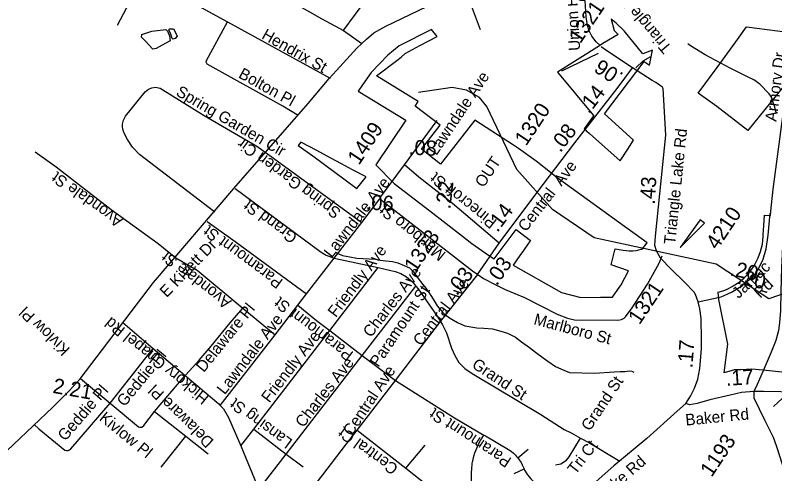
# Model space of a CAD drawing. Extents: x 1715610 to 1720914, y 798298 to 802505.
# Drawn here: x 1715768.9 to 1715906.1, y 799622.4 to 799705.3 of the extents above; entities that cross this region are included whole.
import ezdxf

# ---------------------------------------------------------------- set-up
doc = ezdxf.new("R2010")
doc.units = 0
doc.layers.add('Default', color=7, linetype='Continuous')

msp = doc.modelspace()

# ---------------------------------------------------------------- linework, layer by layer
at = {"layer": 'Default'}
for p, q in [((1715828.11, 799702.49), (1715833.65, 799710.05)), ((1715850.49, 799709.16), (1715852.87, 799702.73)), ((1715807.26, 799704.1), (1715825.78, 799693.93)), ((1715839.23, 799678.27), (1715845.1, 799686.27)), ((1715814.2, 799680.43), (1715831.47, 799667.88)), ((1715834.87, 799672.41), (1715839.23, 799678.27)), ((1715831.47, 799667.88), (1715834.75, 799672.15)), ((1715826.48, 799661.4), (1715831.47, 799667.88)), ((1715852.41, 799658.44), (1715856.31, 799664.11)), ((1715821.52, 799654.94), (1715826.48, 799661.4)), ((1715826.48, 799661.4), (1715834.47, 799659.7)), ((1715825.7, 799648.31), (1715834.47, 799659.7)), ((1715845.7, 799649.97), (1715852.47, 799658.43)), ((1715831.58, 799643.8), (1715841.26, 799656.32)), ((1715819.95, 799652.91), (1715821.52, 799654.94)), ((1715815.84, 799647.56), (1715819.95, 799652.91)), ((1715810, 799652.38), (1715815.84, 799647.56)), ((1715837.55, 799639.28), (1715845.7, 799649.97)), ((1715788.35, 799649.79), (1715793.84, 799645.1)), ((1715805.94, 799634.77), (1715815.84, 799647.56)), ((1715811.99, 799630.49), (1715825.7, 799648.31)), ((1715825.7, 799648.31), (1715831.58, 799643.8)), ((1715786.04, 799635.17), (1715793.84, 799645.1)), ((1715793.84, 799645.1), (1715799.59, 799640.22)), ((1715817.84, 799625.99), (1715831.58, 799643.8)), ((1715831.58, 799643.8), (1715837.55, 799639.28)), ((1715780.67, 799639.65), (1715786.04, 799635.17)), ((1715794.07, 799633.66), (1715799.59, 799640.22)), ((1715830.66, 799630.31), (1715837.55, 799639.28)), ((1715905.84, 799634.58), (1715907.49, 799636.09)), ((1715794.07, 799633.66), (1715799.73, 799629.21)), ((1715809.65, 799627.47), (1715811.99, 799630.49)), ((1715811.99, 799630.49), (1715817.84, 799625.99)), ((1715830.66, 799630.31), (1715839.43, 799623.43)), ((1715795.28, 799623.61), (1715799.73, 799629.21)), ((1715799.73, 799629.21), (1715803.72, 799626.06)), ((1715809.65, 799627.47), (1715812.88, 799619.6)), ((1715839.43, 799623.43), (1715842.93, 799627.63)), ((1715859.67, 799625.33), (1715861.53, 799626.9)), ((1715812.88, 799619.6), (1715817.84, 799625.99)), ((1715817.84, 799625.99), (1715820.91, 799623.71)), ((1715839.43, 799623.43), (1715843.49, 799620.24)), ((1715859.02, 799622.48), (1715860.8, 799623.32))]:
    msp.add_line(p, q, dxfattribs=at)
for points in [[(1715831.51, 799700.23), (1715832.34, 799701), (1715833.68, 799702.12), (1715835.83, 799703.33), (1715846.23, 799708.39), (1715860.3, 799713.75), (1715865.13, 799715.4), (1715867.52, 799716.4), (1715869.21, 799717.62), (1715871.02, 799719.25), (1715879.25, 799726.89), (1715883.32, 799730.86), (1715890.44, 799737.32), (1715894.28, 799741.38)], [(1715788.95, 799724.59), (1715793.74, 799721.98), (1715797.1, 799720.24), (1715801.98, 799717.56), (1715807.32, 799714.53), (1715812.73, 799711.18), (1715818, 799708.29), (1715824.25, 799704.66), (1715828.17, 799702.54), (1715831.51, 799700.23)], [(1715874.55, 799699.85), (1715874.54, 799699.85), (1715873.83, 799700.51), (1715873.06, 799701.55), (1715872.58, 799702.48), (1715872.26, 799703.49), (1715872.02, 799705.03), (1715871.83, 799707.93), (1715871.03, 799707.99), (1715870.56, 799708.22), (1715870.37, 799708.71), (1715870.07, 799710.93), (1715869.79, 799711.87), (1715869.36, 799712.47), (1715869.37, 799713.25), (1715869.78, 799713.9)], [(1715787.37, 799703.55), (1715790.65, 799709.73), (1715792.02, 799712.87)], [(1715792.02, 799712.87), (1715793.45, 799711.92), (1715799.16, 799708.59), (1715807.26, 799704.1)], [(1715820.01, 799687.2), (1715817.22, 799688.86), (1715803.57, 799696.47), (1715803.4, 799696.85), (1715803.46, 799697.15), (1715807.26, 799704.1)], [(1715877.4, 799703.9), (1715876.52, 799704.61), (1715877.07, 799702.55), (1715877.76, 799701.83), (1715875.03, 799700.21), (1715874.4, 799699.81), (1715866.81, 799695), (1715873.31, 799687.17), (1715873.36, 799687.11), (1715871.62, 799684.81), (1715872.59, 799683.97), (1715878.15, 799679), (1715879.52, 799681.13), (1715880.56, 799682.76), (1715875.3, 799687.48), (1715882.5, 799696.94), (1715883.43, 799696.27), (1715884, 799698.98), (1715882.26, 799698.35), (1715878.9, 799702.5), (1715877.4, 799703.9)], [(1715877.4, 799703.9), (1715876.52, 799704.61), (1715877.07, 799702.55), (1715877.76, 799701.83), (1715875.03, 799700.21), (1715874.4, 799699.81), (1715866.81, 799695), (1715873.31, 799687.17), (1715873.36, 799687.11), (1715871.62, 799684.81), (1715872.59, 799683.97), (1715878.15, 799679), (1715879.52, 799681.13), (1715880.56, 799682.76), (1715875.3, 799687.48), (1715882.5, 799696.94), (1715883.43, 799696.27), (1715884, 799698.98), (1715882.26, 799698.35), (1715878.9, 799702.5), (1715877.4, 799703.9)], [(1715793.75, 799699.2), (1715792.39, 799700.72), (1715791.73, 799701.36), (1715791.76, 799701.82), (1715793.55, 799702.46), (1715796.1, 799702.72), (1715796.4, 799702.45), (1715796.77, 799701.59), (1715796.87, 799700.71), (1715795.44, 799699.9), (1715794.34, 799699.28), (1715794.03, 799699.22), (1715793.75, 799699.2)], [(1715797.27, 799701.12), (1715796.96, 799702.08), (1715796.65, 799702.63), (1715796.85, 799702.83), (1715797.46, 799702.83), (1715797.84, 799702.17), (1715798.17, 799701.54), (1715797.81, 799701.1), (1715797.38, 799700.98), (1715797.27, 799701.12)], [(1715830.81, 799691.57), (1715839.44, 799686.37), (1715834.05, 799678.25), (1715837.36, 799674.93), (1715843.8, 799669.96), (1715849.68, 799665.38), (1715851.35, 799664.08), (1715854.37, 799661.96), (1715855.4, 799661.27), (1715859.37, 799666.58), (1715861.97, 799664.61), (1715861.59, 799664.09), (1715860.67, 799662.81), (1715860.02, 799661.88), (1715858.8, 799660.13), (1715867.58, 799655.19), (1715871.05, 799654.31), (1715874.57, 799654.33), (1715876.74, 799654.33), (1715877.03, 799654.72), (1715878.34, 799656.61), (1715879.65, 799659.1), (1715876.54, 799660.18), (1715877.27, 799663.11), (1715878.68, 799662.83), (1715879.22, 799662.77), (1715879.77, 799662.74), (1715880.46, 799662.76), (1715881.01, 799662.82), (1715881.55, 799662.91), (1715881.95, 799663.01), (1715882.11, 799663.04), (1715883.03, 799664.2), (1715881.96, 799664.96), (1715877.85, 799667.89), (1715866.51, 799676.09), (1715865.55, 799676.88), (1715863.01, 799678.91), (1715859.81, 799681.24), (1715858.87, 799681.85), (1715856.01, 799683.7), (1715851.89, 799686.38), (1715845.71, 799678.38), (1715842.29, 799681.11), (1715845.63, 799685.46), (1715841.1, 799688.88), (1715841.68, 799689.75), (1715834.14, 799694.35), (1715837.79, 799697.11), (1715838.63, 799697.75), (1715839.33, 799698.38), (1715841.99, 799699.83), (1715845.11, 799701.48), (1715844.06, 799702.75), (1715838.24, 799699.79), (1715836.2, 799698.07), (1715833.17, 799694.95), (1715831.6, 799692.71), (1715830.81, 799691.57)], [(1715830.81, 799691.57), (1715839.44, 799686.37), (1715834.05, 799678.25), (1715837.36, 799674.93), (1715843.8, 799669.96), (1715849.68, 799665.38), (1715851.35, 799664.08), (1715854.37, 799661.96), (1715855.4, 799661.27), (1715859.37, 799666.58), (1715861.97, 799664.61), (1715861.59, 799664.09), (1715860.67, 799662.81), (1715860.02, 799661.88), (1715858.8, 799660.13), (1715867.58, 799655.19), (1715871.05, 799654.31), (1715874.57, 799654.33), (1715876.74, 799654.33), (1715877.03, 799654.72), (1715878.34, 799656.61), (1715879.65, 799659.1), (1715876.54, 799660.18), (1715877.27, 799663.11), (1715878.68, 799662.83), (1715879.22, 799662.77), (1715879.77, 799662.74), (1715880.46, 799662.76), (1715881.01, 799662.82), (1715881.55, 799662.91), (1715881.95, 799663.01), (1715882.11, 799663.04), (1715883.03, 799664.2), (1715881.96, 799664.96), (1715877.85, 799667.89), (1715866.51, 799676.09), (1715865.55, 799676.88), (1715863.01, 799678.91), (1715859.81, 799681.24), (1715858.87, 799681.85), (1715856.01, 799683.7), (1715851.89, 799686.38), (1715845.71, 799678.38), (1715842.29, 799681.11), (1715845.63, 799685.46), (1715841.1, 799688.88), (1715841.68, 799689.75), (1715834.14, 799694.35), (1715837.79, 799697.11), (1715838.63, 799697.75), (1715839.33, 799698.38), (1715841.99, 799699.83), (1715845.11, 799701.48), (1715844.06, 799702.75), (1715838.24, 799699.79), (1715836.2, 799698.07), (1715833.17, 799694.95), (1715831.6, 799692.71), (1715830.81, 799691.57)], [(1715919.1, 799639.53), (1715903.98, 799641.14), (1715901.84, 799641.35), (1715899.98, 799641.22), (1715898.82, 799641.19), (1715896.95, 799640.7), (1715897.6, 799645.85), (1715895.95, 799653.93), (1715895.83, 799655.24), (1715896.74, 799655.52), (1715897.45, 799655.8), (1715898.37, 799656.26), (1715898.57, 799656.38), (1715899.64, 799657.09), (1715900.52, 799657.82), (1715901.32, 799658.64), (1715902.08, 799659.64), (1715902.56, 799660.48), (1715903.08, 799661.45), (1715903.51, 799662.6), (1715903.83, 799663.91), (1715903.98, 799665.3), (1715904, 799665.64), (1715904.09, 799667.29), (1715904.2, 799669.15), (1715905.29, 799669.09), (1715905.37, 799669.89), (1715905.79, 799673.89), (1715908.36, 799693.36), (1715901.2, 799684.46), (1715895.58, 799688.81), (1715892.25, 799691.21), (1715895.64, 799695.89), (1715899.01, 799700.54), (1715900.95, 799703.22), (1715908.4, 799702.28)], [(1715919.1, 799639.53), (1715903.98, 799641.14), (1715901.84, 799641.35), (1715899.98, 799641.22), (1715898.82, 799641.19), (1715896.95, 799640.7), (1715897.6, 799645.85), (1715895.95, 799653.93), (1715895.83, 799655.24), (1715896.74, 799655.52), (1715897.45, 799655.8), (1715898.37, 799656.26), (1715898.57, 799656.38), (1715899.64, 799657.09), (1715900.52, 799657.82), (1715901.32, 799658.64), (1715902.08, 799659.64), (1715902.56, 799660.48), (1715903.08, 799661.45), (1715903.51, 799662.6), (1715903.83, 799663.91), (1715903.98, 799665.3), (1715904, 799665.64), (1715904.09, 799667.29), (1715904.2, 799669.15), (1715905.29, 799669.09), (1715905.37, 799669.89), (1715905.79, 799673.89), (1715908.36, 799693.36), (1715901.2, 799684.46), (1715895.58, 799688.81), (1715892.25, 799691.21), (1715895.64, 799695.89), (1715899.01, 799700.54), (1715900.95, 799703.22), (1715908.4, 799702.28)], [(1715746.87, 799606.94), (1715750.09, 799610.55), (1715755.24, 799615.32), (1715761.84, 799621.51), (1715764.95, 799624.35), (1715775.71, 799634.47), (1715778.64, 799637.42), (1715780.62, 799639.61), (1715793.86, 799657.02), (1715808.39, 799674), (1715821.8, 799689.38), (1715825.57, 799693.86), (1715826.9, 799695.32), (1715830.61, 799699.38), (1715831.51, 799700.23)], [(1715880.39, 799695.79), (1715875.77, 799698.88), (1715874.72, 799699.58)], [(1715906.34, 799687.75), (1715906.03, 799688.91), (1715905.75, 799689.73), (1715905.48, 799690.5), (1715905.05, 799691.1), (1715903.37, 799692.88), (1715902.29, 799693.62), (1715901.28, 799694.15), (1715900.56, 799694.49), (1715898.01, 799695.76), (1715893.48, 799698.16), (1715890.86, 799699.8), (1715890.36, 799700.14)], [(1715867.59, 799695.24), (1715874.24, 799698.45)], [(1715867.59, 799695.24), (1715874.24, 799698.45)], [(1715880.96, 799695.8), (1715882.28, 799697.05), (1715883.7, 799697.87)], [(1715856.31, 799664.11), (1715863.08, 799673.21), (1715869.97, 799682.23), (1715877.6, 799692.06), (1715880.39, 799695.79)], [(1715892.25, 799653.5), (1715891.76, 799654.84), (1715891.5, 799655.23), (1715889.75, 799657.07), (1715887.38, 799659.44), (1715885.45, 799661.43), (1715884.74, 799662.74), (1715884.44, 799663.68), (1715884.51, 799665.39), (1715886.41, 799683.61), (1715885.89, 799692.1), (1715885.8, 799692.33), (1715885.45, 799692.53), (1715884.57, 799693.13), (1715883.93, 799693.52), (1715880.39, 799695.79)], [(1715804.93, 799669.7), (1715791.35, 799680.17), (1715790.11, 799681.46), (1715789.17, 799682.83), (1715788.53, 799684.15), (1715788.34, 799684.73), (1715788.28, 799685.19), (1715788.29, 799685.64), (1715788.47, 799686.38), (1715788.84, 799687.05), (1715792.36, 799691.45), (1715792.97, 799691.97), (1715793.59, 799692.22), (1715794.25, 799692.29), (1715795.07, 799692.11), (1715803.04, 799687.19), (1715812.54, 799681.64), (1715814.2, 799680.43)], [(1715901.6, 799656.26), (1715895.47, 799660.35), (1715873.43, 799665.08), (1715865.94, 799670.19), (1715859.51, 799677.43), (1715854.07, 799688.85), (1715852.74, 799690.42), (1715850.38, 799691.79), (1715847.82, 799692.24), (1715841.72, 799691.36)], [(1715822.66, 799679.89), (1715830.62, 799673.98), (1715832.25, 799676.09), (1715829.84, 799677.39), (1715827.84, 799678.47), (1715825.92, 799679.49), (1715823.39, 799680.84), (1715820.49, 799682.4), (1715820.02, 799681.77), (1715822.66, 799679.89)], [(1715822.66, 799679.89), (1715830.62, 799673.98), (1715832.25, 799676.09), (1715829.84, 799677.39), (1715827.84, 799678.47), (1715825.92, 799679.49), (1715823.39, 799680.84), (1715820.49, 799682.4), (1715820.02, 799681.77), (1715822.66, 799679.89)], [(1715772.48, 799680.63), (1715776.28, 799677.91), (1715786.22, 799670.21), (1715794.73, 799664.04), (1715797.88, 799661.48)], [(1715856.31, 799664.11), (1715847.85, 799671.31), (1715841.82, 799676.03), (1715839.23, 799678.27)], [(1715808.63, 799673.98), (1715824.18, 799662.47), (1715825.03, 799661.96), (1715826.48, 799661.4)], [(1715834.75, 799672.15), (1715842.01, 799666.47), (1715851.48, 799659.14), (1715852.47, 799658.43)], [(1715892.25, 799653.5), (1715896.4, 799654.41), (1715898.23, 799655.23), (1715900.27, 799656.45), (1715901.65, 799657.72), (1715902.58, 799658.63), (1715903.19, 799659.58), (1715903.95, 799661.24), (1715904.49, 799663.1), (1715904.87, 799665.59), (1715905.21, 799669.56)], [(1715803.54, 799668.06), (1715808.62, 799664.42), (1715821.52, 799654.94)], [(1715888.99, 799663.34), (1715893.36, 799667.71), (1715892.61, 799668.32), (1715888.99, 799663.34)], [(1715888.99, 799663.34), (1715893.36, 799667.71), (1715892.61, 799668.32), (1715888.99, 799663.34)], [(1715907.92, 799666.67), (1715907.49, 799663.53), (1715907.27, 799659.67), (1715907.19, 799655.36), (1715907.08, 799651.92), (1715906.95, 799649.74), (1715906.77, 799648.31), (1715906.28, 799646.53), (1715905.43, 799644.44), (1715903.95, 799641.06), (1715902.9, 799638.56), (1715902.3, 799637.29)], [(1715826.7, 799662.47), (1715827.99, 799661.89), (1715829.35, 799661.63), (1715830.58, 799661.41), (1715831.69, 799661.33), (1715833.99, 799661.21), (1715834.83, 799661.04), (1715835.82, 799660.94), (1715837.04, 799660.78), (1715838.01, 799660.58), (1715839.16, 799660.1), (1715840.08, 799659.67), (1715840.8, 799658.95), (1715841.51, 799657.98), (1715842.53, 799656.63), (1715843.05, 799656.01), (1715843.57, 799655.22), (1715844.07, 799654.5), (1715844.53, 799653.71), (1715845.12, 799652.81), (1715845.81, 799651.97), (1715846.43, 799651.27), (1715847.3, 799650.61), (1715848.79, 799649.78), (1715850.08, 799649.2), (1715851.18, 799649.02), (1715852.25, 799648.8), (1715853.54, 799648.75), (1715855.12, 799648.66), (1715856.57, 799648.23), (1715857.8, 799647.85), (1715859.27, 799647.14), (1715860.32, 799646.3), (1715861.76, 799645.25), (1715862.85, 799644.44), (1715864.23, 799643.37), (1715865.08, 799642.78), (1715866.48, 799641.81), (1715868, 799641.17), (1715869.01, 799640.73), (1715873.54, 799640.59), (1715877.06, 799640.85), (1715878.17, 799640.92), (1715878.98, 799640.94), (1715879.84, 799641.03), (1715880.26, 799640.95), (1715880.63, 799640.8)], [(1715797.88, 799661.48), (1715801.74, 799659.22), (1715810, 799652.38)], [(1715852.47, 799658.43), (1715853.44, 799657.72), (1715855.58, 799656.62), (1715857.39, 799655.74), (1715860.85, 799654.32), (1715866.75, 799651.27), (1715868.61, 799650.55), (1715869.89, 799650.26), (1715877.71, 799650.2), (1715878.37, 799650.29), (1715878.85, 799650.53), (1715879.14, 799650.8), (1715880.29, 799652.42), (1715883.11, 799656.68), (1715885.19, 799660.49), (1715885.74, 799661.8)], [(1715834.47, 799659.7), (1715837.51, 799658.99), (1715838.56, 799658.63), (1715839.59, 799658.03), (1715840.57, 799657.18), (1715841.26, 799656.32)], [(1715948.98, 799649.69), (1715944.54, 799651.19), (1715941.43, 799650.24), (1715936.92, 799647.4), (1715930.32, 799646.42), (1715915.93, 799656.24), (1715913.57, 799656.98), (1715905, 799654.05), (1715901.6, 799656.26)], [(1715841.26, 799656.32), (1715841.65, 799655.84), (1715845.25, 799650.73), (1715845.7, 799649.97)], [(1715819.95, 799652.91), (1715823.34, 799650.12), (1715825.7, 799648.31)], [(1715890.01, 799635.12), (1715890.86, 799636.47), (1715891.59, 799637.91), (1715892.15, 799639.52), (1715892.54, 799641.44), (1715892.83, 799645.03), (1715892.85, 799646.68), (1715892.8, 799650.52), (1715892.56, 799652.25), (1715892.25, 799653.5)], [(1715799.59, 799640.22), (1715800.32, 799640.95), (1715802.11, 799642.95), (1715804.28, 799645.5), (1715807.7, 799649.71), (1715810, 799652.38)], [(1715845.7, 799649.97), (1715846.06, 799649.37), (1715846.78, 799647.89), (1715847.7, 799645.16), (1715848.29, 799643.81), (1715849.03, 799642.56), (1715850.11, 799641.47), (1715851.43, 799640.53), (1715863.81, 799633.12), (1715868.01, 799630.41), (1715869.29, 799629.81), (1715870.98, 799628.88)], [(1715799.59, 799640.22), (1715805.66, 799635.07), (1715805.94, 799634.77)], [(1715837.55, 799639.28), (1715848.24, 799632.54), (1715853.54, 799629.42)], [(1715902.3, 799637.29), (1715900.07, 799637.14), (1715898.03, 799636.62), (1715894.33, 799635.77), (1715892.04, 799635.11), (1715890.73, 799634.88), (1715890.01, 799635.12)], [(1715902.3, 799637.29), (1715902.27, 799636.17), (1715904.22, 799632.17), (1715905.78, 799629.04), (1715906.3, 799627.55), (1715907.07, 799625.31), (1715907.56, 799623.59), (1715907.9, 799621.88), (1715908.13, 799620.24), (1715908.12, 799617.9), (1715908.1, 799614.72)], [(1715909.1, 799637.14), (1715907.16, 799637.22), (1715904.01, 799637.29), (1715902.3, 799637.29)], [(1715772.41, 799631.3), (1715773.17, 799630.55), (1715777.88, 799626.71), (1715778.15, 799626.63), (1715778.44, 799626.64), (1715778.7, 799626.75), (1715778.93, 799626.94), (1715786.04, 799635.17)], [(1715786.04, 799635.17), (1715791.14, 799630.94), (1715791.43, 799630.85), (1715791.76, 799630.88), (1715792.13, 799631.13), (1715794.07, 799633.66)], [(1715890.01, 799635.12), (1715888.45, 799633.74), (1715882.95, 799628.79), (1715877.02, 799623.84), (1715871.14, 799618.71), (1715864.33, 799612.97), (1715862.85, 799611.55), (1715857.18, 799605.08), (1715851.79, 799598.24), (1715846.32, 799591.23), (1715843.76, 799587.75)], [(1715805.94, 799634.77), (1715806.49, 799634.15), (1715807.39, 799632.59), (1715809.65, 799627.47)], [(1715816.12, 799611.63), (1715818.03, 799613.96), (1715824.46, 799622.22), (1715828.54, 799627.62), (1715830.66, 799630.31)], [(1715852.04, 799618.46), (1715851.84, 799619.02), (1715851.48, 799620.28), (1715851.39, 799620.82), (1715851.33, 799621.38), (1715851.3, 799621.76), (1715851.29, 799622.15), (1715851.3, 799622.72), (1715851.34, 799623.29), (1715851.44, 799624.2), (1715851.51, 799624.6), (1715851.59, 799625.01), (1715851.74, 799625.61), (1715851.92, 799626.19), (1715852.12, 799626.78), (1715852.37, 799627.34), (1715852.63, 799627.9), (1715852.93, 799628.43), (1715853.54, 799629.42)], [(1715853.54, 799629.42), (1715853.81, 799629.26), (1715857.99, 799626.81), (1715858.44, 799626.5), (1715858.91, 799626.13), (1715859.26, 799625.8), (1715859.45, 799625.58), (1715859.67, 799625.33)], [(1715866.47, 799624.03), (1715867.43, 799624.2), (1715868.43, 799624.88), (1715868.92, 799625.47), (1715870.98, 799628.88)], [(1715870.98, 799628.88), (1715872.51, 799628.08), (1715878.08, 799624.72)], [(1715859.67, 799625.33), (1715859.93, 799624.97), (1715860.25, 799624.48), (1715860.48, 799624.06), (1715860.8, 799623.32)], [(1715860.8, 799623.32), (1715860.9, 799623.1), (1715861.01, 799622.9), (1715861.32, 799622.4), (1715861.64, 799621.96), (1715862, 799621.54), (1715862.38, 799621.16), (1715862.81, 799620.81), (1715862.99, 799620.67), (1715863.73, 799620.2)]]:
    msp.add_lwpolyline(points, dxfattribs=at)

# ---------------------------------------------------------------- texts
for s, height, rotation, p in [('Triangle Lake Rd', 2.0663, 130.2684, (1715887.59, 799699.5)), ('Union Hill Ct', 2.0663, 93.2309, (1715870.95, 799698.94)), ('1321', 2.719, 56.2051, (1715870.94, 799700.04)), ('Hendrix St', 2.066, 330.4741, (1715813.25, 799701.2)), ('Armory Dr', 2.066, 82.5782, (1715906.36, 799686.01)), ('.06', 2.719, 146.1702, (1715878.92, 799694.71)), ('Bolton Pl', 2.066, 330.8692, (1715809.06, 799694.14)), ('Lawndale Ave', 2.0663, 56.2051, (1715844.97, 799679.84)), ('.14', 2.719, 52.1742, (1715872.52, 799687.35)), ('Spring Garden Cir', 2.0663, 329.6562, (1715797.76, 799690.95)), ('1320', 2.719, 56.2051, (1715861.16, 799681.55)), ('1409', 2.719, 56.2051, (1715830.98, 799678.1)), ('.08', 2.719, 52.3595, (1715867.35, 799680.37)), ('Triangle Lake Rd', 2.0663, 84.031, (1715888.07, 799663.8)), ('Spring Garden Cir', 2.0663, 143.5611, (1715827.89, 799670.03)), ('.08', 2.719, 357.5478, (1715839.93, 799680.12)), ('OUT', 2.066, 56.2051, (1715853.47, 799674.03)), ('Central  Ave', 2.0663, 52.1888, (1715861.13, 799666.04)), ('Avondale St', 2.0663, 144.3486, (1715788.54, 799668.48)), ('Pinecroft St', 2.0663, 141.4159, (1715856.05, 799668.18)), ('Lawndale Ave', 2.0663, 52.1626, (1715826.07, 799661.33)), ('.22', 2.719, 83.413, (1715847.49, 799670.18)), ('.43', 2.719, 86.4557, (1715884.39, 799671.03)), ('Grand St', 2.066, 143.7404, (1715820.03, 799665.56)), ('.06', 2.719, 357.1316, (1715832.14, 799670.19)), ('Marlboro St', 2.0663, 141.0359, (1715846.82, 799662.32)), ('.14', 2.719, 53.3448, (1715855.99, 799665.95)), ('4210', 2.719, 56.2051, (1715895.68, 799662.78)), ('Paramount St', 2.0663, 143.3367, (1715817.42, 799657.39)), ('1323', 2.719, 56.2051, (1715841.18, 799658.66)), ('E Kivett Dr', 2.0663, 45.8944, (1715796.26, 799654.18)), ('Avondale St', 2.0663, 142.0597, (1715808.1, 799653.67)), ('Friendly Ave', 2.0663, 52.7293, (1715826.8, 799650.56)), ('.03', 2.719, 55.4793, (1715855.88, 799656.29)), ('Charles Ave', 2.0663, 52.1894, (1715833.14, 799646.94)), ('.03', 2.719, 51.5738, (1715848.66, 799654.47)), ('.20', 2.719, 348.0435, (1715897.81, 799658.32)), ('Jamac', 2.066, 43.519, (1715899.53, 799653.99)), ('.20', 2.719, 348.0435, (1715899.18, 799656.81)), ('Central Ave', 2.0663, 52.3531, (1715842.19, 799645.39)), ('1321', 2.719, 56.2051, (1715881.64, 799649.24)), (' Rd', 2.066, 43.519, (1715902.88, 799653.51)), ('Paramount St', 2.0663, 56.2051, (1715834.48, 799641.57)), ('Paramount St', 2.0663, 142.7388, (1715830.13, 799644.31)), ('Delaware Pl', 2.0663, 51.0014, (1715802.95, 799640.63)), ('Kivlow Pl', 2.066, 135.906, (1715778.91, 799645.02)), ('Marlboro St', 2.0663, 345.068, (1715862.41, 799649.48)), ('Hickory Chapel Rd', 2.0663, 140.9342, (1715804.06, 799636.38)), ('Lawndale Ave', 2.0663, 52.1626, (1715806.74, 799636.6)), ('Friendly Ave', 2.0663, 52.444, (1715814.79, 799635.12)), ('.17', 2.719, 85.3344, (1715891.18, 799641.47)), ('Geddie Pl', 2.066, 50.6316, (1715788.65, 799634.43)), ('Charles Ave', 2.0663, 51.8038, (1715820.9, 799630.65)), ('Grand St', 2.066, 326.5575, (1715851.22, 799641.73)), ('Central Ave', 2.0663, 56.2051, (1715829.65, 799629.11)), ('.17', 2.719, 3.7399, (1715897.29, 799638.32)), ('2.21', 2.719, 349.9325, (1715775.56, 799637.07)), ('Grand St', 2.066, 56.2051, (1715872.66, 799630.01)), ('Geddie Pl', 2.066, 49.1534, (1715777.93, 799628.21)), ('Delaware Pl', 2.0663, 135.9657, (1715804.9, 799628.39)), ('Lansing St', 2.066, 143.4364, (1715819.14, 799628.47)), ('Kivlow Pl', 2.066, 320.7209, (1715783.93, 799632.23)), ('Paramount St', 2.0663, 146.5321, (1715858.68, 799625.14)), ('Baker Rd', 2.066, 5.6329, (1715890.03, 799631.13)), ('Central Ct', 2.066, 144.0273, (1715838.24, 799623.75)), ('1193', 2.719, 56.2051, (1715894.66, 799621.69)), ('Tri Ct', 2.066, 52.3531, (1715870.09, 799622.16)), ('Triangle Lake Rd', 2.0663, 40.968, (1715867.09, 799610.56))]:
    msp.add_text(s, height=height, rotation=rotation, dxfattribs=at).set_placement(p)

doc.saveas('drawing.dxf')
